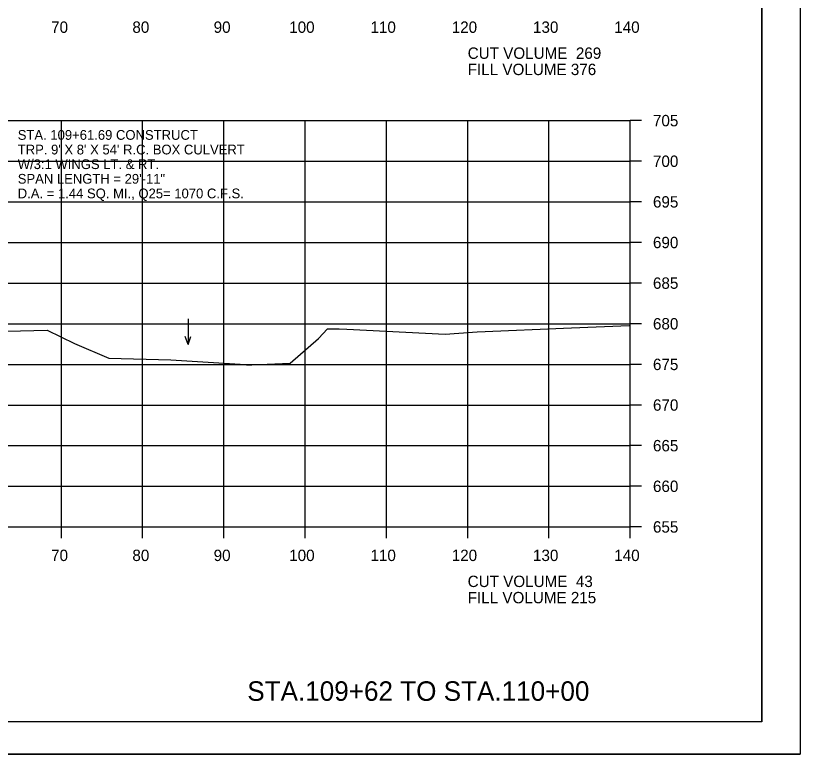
# Model space of a CAD drawing. Extents: x 1360146 to 1361431, y 631444 to 632352.
# Drawn here: x 1360383.1 to 1360479.7, y 631870.8 to 631961.7 of the extents above; entities that cross this region are included whole.
import ezdxf

# ---------------------------------------------------------------- set-up
doc = ezdxf.new("R2010")
doc.units = 0
for name, color, linetype in [('R_Axis', 7, 'Continuous'), ('R_Axis Annot', 7, 'Continuous'), ('R_Border', 7, 'Continuous'), ('R_Draft', 7, 'Continuous'), ('R_Exist Surface', 7, 'Continuous'), ('R_Grid', 7, 'Continuous'), ('R_No Plot', 7, 'Continuous'), ('R_Water', 7, 'Continuous'), ('R_Water Annot', 7, 'Continuous')]:
    doc.layers.add(name, color=color, linetype=linetype)

msp = doc.modelspace()

# ---------------------------------------------------------------- linework, layer by layer
at = {"layer": 'R_Axis'}
for p, q in [((1360458.771, 631898.82), (1360458.771, 631948.82)), ((1360460.171, 631948.82), (1360458.771, 631948.82)), ((1360460.171, 631943.82), (1360458.771, 631943.82)), ((1360460.171, 631938.82), (1360458.771, 631938.82)), ((1360460.171, 631933.82), (1360458.771, 631933.82)), ((1360460.171, 631928.82), (1360458.771, 631928.82)), ((1360460.171, 631923.82), (1360458.771, 631923.82)), ((1360460.171, 631918.82), (1360458.771, 631918.82)), ((1360460.171, 631913.82), (1360458.771, 631913.82)), ((1360460.171, 631908.82), (1360458.771, 631908.82)), ((1360460.171, 631903.82), (1360458.771, 631903.82)), ((1360178.771, 631898.82), (1360458.771, 631898.82)), ((1360388.771, 631897.42), (1360388.771, 631898.82)), ((1360398.771, 631897.42), (1360398.771, 631898.82)), ((1360408.771, 631897.42), (1360408.771, 631898.82)), ((1360418.771, 631897.42), (1360418.771, 631898.82)), ((1360428.771, 631897.42), (1360428.771, 631898.82)), ((1360438.771, 631897.42), (1360438.771, 631898.82)), ((1360448.771, 631897.42), (1360448.771, 631898.82)), ((1360458.771, 631897.42), (1360458.771, 631898.82)), ((1360460.171, 631898.82), (1360458.771, 631898.82))]:
    msp.add_line(p, q, dxfattribs=at)
at = {"layer": 'R_Border'}
for q in [(1360474.951, 632080.28), (1360158.771, 631874.82)]:
    msp.add_line((1360474.951, 631874.82), q, dxfattribs=at)
at = {"layer": 'R_Exist Surface'}
msp.add_lwpolyline([(1360377.142, 631922.784), (1360387.04, 631923.014), (1360390.387, 631921.41), (1360394.597, 631919.59), (1360402.232, 631919.388), (1360410.789, 631918.848), (1360411.54, 631918.767), (1360411.79, 631918.755), (1360412.207, 631918.782), (1360416.92, 631918.956), (1360420.42, 631922.024), (1360421.529, 631923.19), (1360422.949, 631923.197), (1360423.908, 631923.17), (1360435.987, 631922.53), (1360439.95, 631922.845), (1360451.564, 631923.321), (1360458.649, 631923.612), (1360458.771, 631923.621)], dxfattribs=at)
at = {"layer": 'R_Grid'}
for p, q in [((1360178.771, 631948.82), (1360458.771, 631948.82)), ((1360388.771, 631898.82), (1360388.771, 631948.82)), ((1360398.771, 631898.82), (1360398.771, 631948.82)), ((1360408.771, 631898.82), (1360408.771, 631948.82)), ((1360418.771, 631898.82), (1360418.771, 631948.82)), ((1360428.771, 631898.82), (1360428.771, 631948.82)), ((1360438.771, 631898.82), (1360438.771, 631948.82)), ((1360448.771, 631898.82), (1360448.771, 631948.82)), ((1360458.771, 631898.82), (1360458.771, 631948.82)), ((1360178.771, 631943.82), (1360458.771, 631943.82)), ((1360178.771, 631938.82), (1360458.771, 631938.82)), ((1360178.771, 631933.82), (1360458.771, 631933.82)), ((1360178.771, 631928.82), (1360458.771, 631928.82)), ((1360178.771, 631923.82), (1360458.771, 631923.82)), ((1360178.771, 631918.82), (1360458.771, 631918.82)), ((1360178.771, 631913.82), (1360458.771, 631913.82)), ((1360178.771, 631908.82), (1360458.771, 631908.82)), ((1360178.771, 631903.82), (1360458.771, 631903.82)), ((1360178.771, 631898.82), (1360458.771, 631898.82))]:
    msp.add_line(p, q, dxfattribs=at)
at = {"layer": 'R_No Plot'}
msp.add_line((1360146.37, 631870.842), (1360479.703, 631870.842), dxfattribs=at)
for points in [[(1360146.363, 632084.175), (1360479.703, 632084.175), (1360479.703, 631870.837), (1360146.363, 631870.837)], [(1360392.691, 632080.28), (1360392.691, 632070.4), (1360428.423, 632070.4), (1360428.423, 632067.48), (1360451.622, 632067.48), (1360451.622, 632043.148), (1360474.951, 632043.148), (1360474.951, 631874.82), (1360158.771, 631874.82), (1360158.771, 632080.28)]]:
    msp.add_lwpolyline(points, close=True, dxfattribs=at)
at = {"layer": 'R_Water Annot'}
for p, q in [((1360404.353, 631924.421), (1360404.353, 631921.279)), ((1360404.353, 631921.279), (1360404.003, 631922.24)), ((1360404.353, 631921.279), (1360404.703, 631922.24))]:
    msp.add_line(p, q, dxfattribs=at)

# ---------------------------------------------------------------- texts
at = {"layer": 'R_Axis Annot'}
for s, p in [('70', (1360387.509, 631959.62)), ('80', (1360397.509, 631959.62)), ('90', (1360407.509, 631959.62)), ('100', (1360416.809, 631959.62)), ('110', (1360426.809, 631959.62)), ('120', (1360436.809, 631959.62)), ('130', (1360446.809, 631959.62)), ('140', (1360456.809, 631959.62)), ('CUT VOLUME  269', (1360438.771, 631956.42)), ('FILL VOLUME 376', (1360438.771, 631954.42)), ('705', (1360461.571, 631948.12)), ('700', (1360461.571, 631943.12)), ('695', (1360461.571, 631938.12)), ('690', (1360461.571, 631933.12)), ('685', (1360461.571, 631928.12)), ('680', (1360461.571, 631923.12)), ('675', (1360461.571, 631918.12)), ('670', (1360461.571, 631913.12)), ('665', (1360461.571, 631908.12)), ('660', (1360461.571, 631903.12)), ('655', (1360461.571, 631898.12)), ('70', (1360387.509, 631894.62)), ('80', (1360397.509, 631894.62)), ('90', (1360407.509, 631894.62)), ('100', (1360416.809, 631894.62)), ('110', (1360426.809, 631894.62)), ('120', (1360436.809, 631894.62)), ('130', (1360446.809, 631894.62)), ('140', (1360456.809, 631894.62)), ('CUT VOLUME  43', (1360438.771, 631891.42)), ('FILL VOLUME 215', (1360438.771, 631889.42))]:
    msp.add_text(s, height=1.4, dxfattribs=at).set_placement(p)
at = {"layer": 'R_Draft'}
msp.add_text('STA.109+62 TO STA.110+00', height=2.4, dxfattribs=at).set_placement((1360411.646, 631877.42))
at = {"layer": 'R_Water'}
for s, p in [('STA. 109+61.69 CONSTRUCT', (1360383.402, 631946.458)), ("TRP. 9' X 8' X 54' R.C. BOX CULVERT", (1360383.402, 631944.658)), ('W/3:1 WINGS LT. & RT. ', (1360383.402, 631942.858)), ('SPAN LENGTH = 29\'-11"', (1360383.402, 631941.058)), ('D.A. = 1.44 SQ. MI., Q25= 1070 C.F.S. ', (1360383.402, 631939.258))]:
    msp.add_text(s, height=1.2, dxfattribs=at).set_placement(p)

doc.saveas('drawing.dxf')
